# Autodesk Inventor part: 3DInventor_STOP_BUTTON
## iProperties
Created: 2006-11
Part Number: 3DInventor_STOP_BUTTON
Document SubType Name: Modeling
Designer: conardl1
Density: 1 g/cm^3
DESCRIPTION: Stop Button
MODELED_BY: L Conard
Author: conardl1
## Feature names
1. Base1
